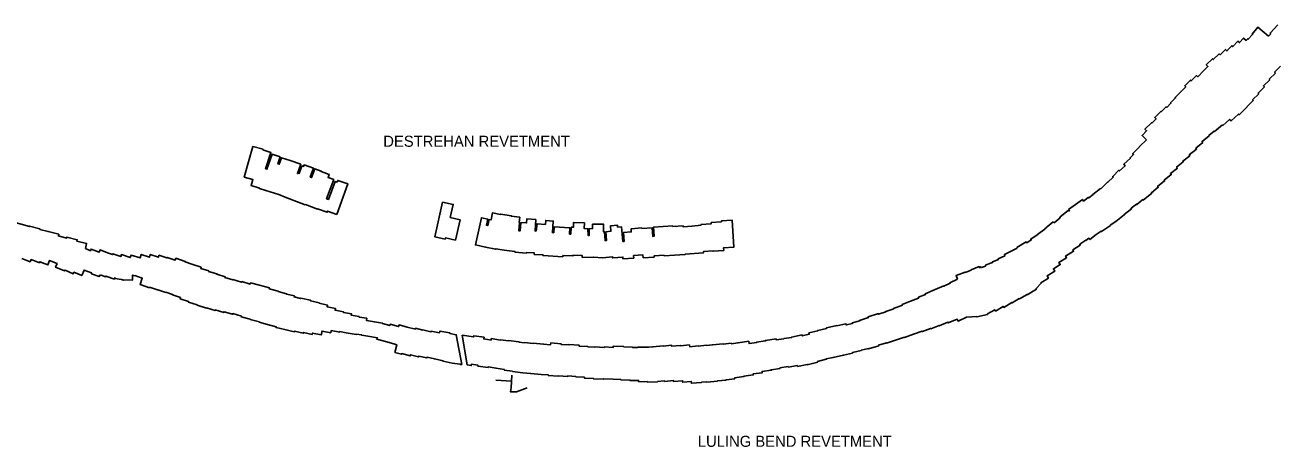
# Model space of a CAD drawing. Extents: x 2650582 to 3923188, y 277893 to 989177.
# Drawn here: x 3587538 to 3605630, y 520725 to 526834 of the extents above; entities that cross this region are included whole.
import ezdxf

# ---------------------------------------------------------------- set-up
doc = ezdxf.new("R2010")
doc.units = 0
doc.layers.add('Level 3', color=7, linetype='Continuous')

msp = doc.modelspace()

# ---------------------------------------------------------------- linework, layer by layer
at = {"layer": 'Level 3'}
for p, q in [((3597395, 522195), (3597395, 522195)), ((3594345, 521695), (3594574, 521678))]:
    msp.add_line(p, q, dxfattribs=at)
for points in [[(3605524, 526674), (3605370, 526803), (3605285, 526702), (3605293, 526694), (3605230, 526627), (3605223, 526634), (3605201, 526611), (3605163, 526645), (3605103, 526578), (3605081, 526599), (3605005, 526520), (3604991, 526534), (3604920, 526459), (3604898, 526481), (3604821, 526403), (3604808, 526416), (3604724, 526332), (3604711, 526346), (3604623, 526258), (3604647, 526234), (3604580, 526168), (3604580, 526168), (3604498, 526085), (3604480, 526102), (3604403, 526025), (3604392, 526036), (3604310, 525954), (3604326, 525938), (3604260, 525872), (3604258, 525873), (3604171, 525785), (3604178, 525777), (3604107, 525706), (3604112, 525701), (3604051, 525640), (3604042, 525650), (3603970, 525578), (3603966, 525582), (3603878, 525495), (3603897, 525476), (3603835, 525414), (3603830, 525419), (3603736, 525326), (3603760, 525302), (3603694, 525236), (3603757, 525173)], [(3605656, 526834), (3605545, 526717), (3605555, 526707), (3605524, 526674)], [(3604858, 525387), (3604864, 525380), (3604960, 525468), (3604982, 525445), (3605089, 525543), (3605098, 525534), (3605213, 525647), (3605209, 525651), (3605301, 525742), (3605293, 525751), (3605382, 525839), (3605372, 525849), (3605462, 525938), (3605448, 525952), (3605540, 526042), (3605532, 526049), (3605623, 526138), (3605609, 526152), (3605697, 526238)], [(3604574, 525131), (3604561, 525148), (3604663, 525229), (3604659, 525234), (3604736, 525296), (3604740, 525291), (3604858, 525387)], [(3590831, 525075), (3590709, 524630), (3590834, 524596), (3590807, 524512), (3590929, 524470), (3590928, 524466), (3591019, 524436), (3591207, 524378), (3591300, 524343), (3591299, 524340), (3591591, 524231), (3591593, 524234), (3591766, 524169), (3591769, 524174), (3591907, 524123), (3591913, 524139), (3592049, 524092)], [(3592049, 524092), (3592206, 524536), (3592060, 524585), (3592050, 524559), (3592021, 524568), (3591925, 524310), (3591900, 524319), (3592002, 524596), (3591922, 524625), (3591938, 524669), (3591820, 524713), (3591821, 524719), (3591730, 524752), (3591682, 524625), (3591664, 524631), (3591710, 524760), (3591574, 524808), (3591566, 524786), (3591542, 524794), (3591501, 524682), (3591486, 524687), (3591483, 524682), (3591478, 524684), (3591526, 524817), (3591373, 524873), (3591371, 524870), (3591247, 524912), (3591215, 524817), (3591196, 524823), (3591227, 524923), (3591110, 524962), (3591037, 524745), (3591016, 524752), (3591094, 524989), (3590979, 525027), (3590981, 525035), (3590831, 525075)], [(3601460, 522642), (3601458, 522651), (3601564, 522711), (3601576, 522692), (3601687, 522760), (3601695, 522747), (3601809, 522817), (3601813, 522810), (3601918, 522874), (3601922, 522868), (3602030, 522934), (3602033, 522930), (3602166, 523012), (3602161, 523020), (3602236, 523098), (3602230, 523104), (3602338, 523170), (3602319, 523201), (3602434, 523271), (3602412, 523305), (3602511, 523366), (3602492, 523397), (3602603, 523465), (3602588, 523489), (3602702, 523559), (3602690, 523579), (3602800, 523647), (3602792, 523660), (3602879, 523720), (3602882, 523716), (3602925, 523746), (3602940, 523728), (3603030, 523801), (3603102, 523850), (3603106, 523844), (3603235, 523932), (3603233, 523934), (3603313, 523989), (3603315, 523987), (3603437, 524084), (3603433, 524089), (3603540, 524174), (3603534, 524181), (3603611, 524242), (3603617, 524235), (3603705, 524306), (3603710, 524300), (3603834, 524399), (3603830, 524405), (3603928, 524484), (3603919, 524496), (3604020, 524576), (3604013, 524586), (3604115, 524668), (3604104, 524682), (3604205, 524763), (3604194, 524778), (3604290, 524855), (3604284, 524863), (3604383, 524942), (3604375, 524952), (3604483, 525037), (3604472, 525050), (3604574, 525131)], [(3603757, 525173), (3603655, 525073), (3603657, 525071), (3603556, 524971), (3603570, 524957), (3603520, 524911), (3603525, 524906), (3603429, 524817), (3603448, 524796), (3603367, 524721), (3603358, 524730), (3603269, 524642), (3603278, 524633), (3603199, 524557), (3603196, 524560), (3603096, 524464), (3603094, 524466), (3602982, 524382), (3602985, 524378), (3602922, 524331), (3602916, 524339), (3602847, 524286), (3602831, 524308), (3602730, 524237), (3602731, 524236), (3602628, 524164)], [(3593578, 524270), (3593463, 523768), (3593615, 523734), (3593619, 523752), (3593762, 523720)], [(3593762, 523720), (3593830, 524015), (3593688, 524048), (3593732, 524236), (3593578, 524270)], [(3602628, 524164), (3602644, 524142), (3602640, 524140), (3602630, 524153), (3602504, 524050), (3602510, 524043), (3602421, 523971), (3602410, 523984), (3602322, 523911), (3602307, 523902), (3602308, 523900), (3602285, 523881), (3602286, 523880), (3602188, 523806), (3602190, 523805), (3602084, 523734), (3602092, 523722), (3602025, 523681), (3602017, 523694), (3601883, 523612), (3601888, 523605)], [(3588411, 523597), (3588427, 523673), (3588289, 523703), (3588294, 523725), (3588141, 523761), (3588138, 523750), (3588020, 523780), (3588026, 523806), (3587873, 523845), (3587872, 523843), (3587753, 523875), (3587754, 523881), (3587602, 523923), (3587601, 523917), (3587481, 523950), (3587481, 523951), (3587344, 523988), (3587345, 523992), (3587220, 524027), (3587223, 524036), (3587090, 524079)], [(3595318, 523498), (3595316, 523479), (3595031, 523496), (3595031, 523505), (3594902, 523514), (3594903, 523535), (3594791, 523542), (3594790, 523533), (3594622, 523546), (3594622, 523556), (3594470, 523573), (3594348, 523594), (3594346, 523588), (3594198, 523619), (3594198, 523616), (3594052, 523650), (3594138, 524043), (3594229, 524023), (3594212, 523934), (3594231, 523930), (3594250, 524019), (3594279, 524013), (3594301, 524115), (3594416, 524091), (3594417, 524097), (3594569, 524073), (3594569, 524065), (3594694, 524050), (3594686, 523976), (3594690, 523976), (3594681, 523854), (3594699, 523852), (3594709, 523973), (3594791, 523968), (3594795, 524027), (3594925, 524018), (3594914, 523852), (3594932, 523850), (3594943, 523958), (3595064, 523948), (3595069, 524004), (3595177, 523996), (3595165, 523828), (3595185, 523827), (3595192, 523913), (3595415, 523900), (3595413, 523808), (3595432, 523807)], [(3595432, 523807), (3595437, 523905), (3595468, 523905), (3595471, 523975), (3595628, 523968), (3595625, 523886), (3595679, 523885), (3595681, 523787), (3595699, 523788), (3595699, 523884), (3595746, 523886), (3595747, 523949), (3595902, 523952), (3595903, 523840), (3595917, 523841), (3595926, 523712), (3595946, 523713), (3595939, 523842), (3596011, 523848), (3596007, 523928), (3596107, 523936), (3596109, 523909), (3596164, 523913), (3596182, 523700), (3596201, 523701), (3596192, 523829), (3596306, 523839), (3596305, 523884), (3596458, 523897), (3596460, 523889), (3596607, 523898), (3596617, 523774), (3596635, 523775), (3596626, 523906), (3596906, 523925), (3596907, 523918), (3597056, 523928), (3597058, 523912), (3597184, 523921), (3597183, 523924), (3597315, 523935), (3597314, 523947), (3597462, 523958), (3597462, 523974), (3597610, 523986), (3597609, 523999), (3597765, 524010), (3597790, 523619), (3597642, 523610), (3597644, 523570), (3597488, 523558), (3597488, 523564), (3597350, 523553), (3597351, 523536), (3597084, 523515), (3597084, 523510), (3596930, 523500), (3596929, 523504), (3596780, 523494), (3596780, 523502), (3596635, 523492), (3596636, 523475), (3596479, 523464), (3596474, 523506), (3596340, 523496), (3596341, 523461), (3596186, 523451), (3596184, 523474), (3596038, 523462), (3596036, 523477), (3595891, 523465), (3595759, 523474), (3595758, 523471), (3595598, 523470), (3595597, 523497), (3595462, 523502), (3595462, 523492), (3595318, 523498)], [(3601888, 523605), (3601801, 523559), (3601801, 523558), (3601703, 523511), (3601711, 523493), (3601612, 523449), (3601617, 523438), (3601529, 523404), (3601531, 523397), (3601489, 523381), (3601488, 523383), (3601477, 523376), (3601430, 523358), (3601433, 523349), (3601416, 523339), (3601373, 523323), (3601366, 523333), (3601344, 523319), (3601338, 523336), (3601222, 523291), (3601224, 523286), (3601136, 523252), (3601134, 523257), (3601004, 523206), (3601023, 523156)], [(3587492, 523454), (3587612, 523406), (3587625, 523439), (3587745, 523392), (3587751, 523408), (3587870, 523361), (3587894, 523425), (3588002, 523380), (3587980, 523327), (3588111, 523273), (3588116, 523285), (3588235, 523234), (3588244, 523254), (3588357, 523206), (3588392, 523287), (3588501, 523245), (3588497, 523234), (3588610, 523192), (3588618, 523215), (3588635, 523208)], [(3588731, 523536), (3588623, 523578), (3588610, 523544), (3588492, 523590), (3588483, 523567), (3588411, 523597)], [(3593857, 521918), (3593775, 522350), (3593682, 522368), (3593683, 522376), (3593538, 522404), (3593533, 522378), (3593410, 522402), (3593408, 522392), (3593290, 522419), (3593290, 522417), (3593186, 522444), (3593183, 522432), (3593067, 522462), (3593066, 522461), (3592947, 522493), (3592941, 522469), (3592818, 522503), (3592813, 522482), (3592708, 522511), (3592709, 522516), (3592590, 522535), (3592591, 522538), (3592475, 522557), (3592480, 522588), (3592369, 522606), (3592370, 522614), (3592257, 522632), (3592261, 522652), (3592143, 522674), (3592144, 522681), (3592021, 522705), (3592027, 522732), (3591906, 522755), (3591911, 522780), (3591793, 522805), (3591794, 522812), (3591667, 522841), (3591669, 522849), (3591525, 522882), (3591523, 522874), (3591429, 522897), (3591433, 522913), (3591320, 522940), (3591321, 522944), (3591200, 522977), (3591200, 522979), (3591069, 523015), (3591073, 523029), (3590929, 523068), (3590929, 523066), (3590800, 523101), (3590795, 523083), (3590674, 523120), (3590671, 523110), (3590542, 523148), (3590541, 523143), (3590430, 523177), (3590434, 523190), (3590311, 523227), (3590312, 523232), (3590192, 523268), (3590194, 523273), (3590079, 523310), (3590085, 523328), (3589951, 523374), (3589950, 523372), (3589852, 523405), (3589854, 523411), (3589719, 523457), (3589711, 523431), (3589594, 523470), (3589591, 523462), (3589475, 523501), (3589466, 523473), (3589350, 523512), (3589336, 523472), (3589219, 523514), (3589201, 523462), (3589072, 523504), (3589060, 523467), (3588931, 523510), (3588922, 523482), (3588810, 523522), (3588805, 523510), (3588731, 523536)], [(3588635, 523208), (3588637, 523213), (3588704, 523189), (3588708, 523200), (3588830, 523157), (3588837, 523178), (3588835, 523165), (3588932, 523149), (3588960, 523140), (3588961, 523143), (3589092, 523140), (3589094, 523214), (3589124, 523204), (3589125, 523206), (3589233, 523167), (3589203, 523077), (3589338, 523031), (3589340, 523037), (3589456, 522998), (3589457, 523001), (3589572, 522962), (3589573, 522966), (3589672, 522933), (3589670, 522927), (3589786, 522887), (3589781, 522871), (3589904, 522830), (3589901, 522822), (3590029, 522782), (3590028, 522776), (3590163, 522735), (3590164, 522738), (3590287, 522701), (3590289, 522709), (3590413, 522672), (3590416, 522683), (3590540, 522646), (3590543, 522656), (3590668, 522618), (3590666, 522609), (3590795, 522574), (3590794, 522573), (3590927, 522537), (3590926, 522533), (3591047, 522500), (3591046, 522497), (3591171, 522464), (3591169, 522455), (3591313, 522420), (3591313, 522422), (3591431, 522393), (3591433, 522401), (3591561, 522372), (3591564, 522384), (3591691, 522355), (3591696, 522375), (3591822, 522349), (3591833, 522403), (3591960, 522379), (3591966, 522411), (3592089, 522388), (3592090, 522396), (3592182, 522378), (3592182, 522378), (3592328, 522354), (3592329, 522361), (3592409, 522348), (3592408, 522342), (3592555, 522318), (3592555, 522320), (3592633, 522307), (3592627, 522286), (3592750, 522252), (3592750, 522251), (3592873, 522218), (3592872, 522218), (3592917, 522206), (3592887, 522095), (3592984, 522068), (3592986, 522077), (3593109, 522045), (3593113, 522060), (3593229, 522029), (3593232, 522040), (3593349, 522014), (3593352, 522024), (3593459, 522003), (3593458, 522000), (3593585, 521975), (3593583, 521967), (3593715, 521941), (3593715, 521940), (3593830, 521924), (3593830, 521921), (3593857, 521918)], [(3601023, 523156), (3600915, 523104), (3600920, 523095), (3600828, 523051), (3600825, 523058), (3600699, 523003), (3600699, 523005), (3600558, 522944), (3600563, 522933), (3600458, 522892), (3600462, 522882), (3600343, 522835), (3600343, 522835), (3600224, 522790), (3600228, 522780), (3600100, 522732), (3600103, 522726), (3599987, 522689), (3599989, 522682), (3599883, 522648), (3599880, 522657), (3599732, 522610), (3599736, 522599), (3599607, 522558), (3599609, 522551), (3599504, 522524), (3599506, 522515), (3599414, 522492), (3599410, 522509), (3599280, 522480), (3599280, 522483), (3599129, 522449), (3599131, 522442), (3599003, 522414), (3599005, 522408), (3598875, 522376), (3598879, 522358), (3598779, 522333), (3598777, 522347), (3598625, 522316), (3598626, 522311), (3598513, 522294), (3598514, 522292), (3598402, 522275), (3598400, 522289), (3598247, 522269), (3598248, 522262), (3598119, 522245), (3598120, 522236), (3598009, 522222), (3598004, 522256), (3597850, 522235), (3597851, 522232), (3597753, 522219), (3597752, 522228), (3597634, 522216), (3597634, 522219), (3597480, 522206), (3597480, 522202), (3597395, 522195)], [(3597396, 521670), (3597397, 521666), (3597551, 521679), (3597551, 521683), (3597676, 521693), (3597676, 521700), (3597802, 521713), (3597801, 521726), (3597936, 521745), (3597936, 521752), (3598069, 521769), (3598067, 521783), (3598201, 521801), (3598199, 521819), (3598330, 521837), (3598329, 521843), (3598458, 521861), (3598456, 521872), (3598575, 521890), (3598576, 521883), (3598710, 521904), (3598712, 521891), (3598850, 521920), (3598851, 521915), (3599002, 521951), (3598999, 521964), (3599126, 521995), (3599124, 522000), (3599225, 522023), (3599225, 522020), (3599376, 522053), (3599375, 522057), (3599505, 522086), (3599504, 522091), (3599632, 522124), (3599632, 522125), (3599735, 522151), (3599737, 522145), (3599885, 522192), (3599883, 522200), (3599995, 522235), (3599996, 522230), (3600144, 522277), (3600144, 522278), (3600257, 522314), (3600259, 522309), (3600386, 522357), (3600386, 522357), (3600513, 522404), (3600517, 522395), (3600636, 522441), (3600638, 522437), (3600758, 522484), (3600760, 522479), (3600886, 522534), (3600891, 522522), (3601018, 522578), (3601032, 522548), (3601153, 522605), (3601154, 522604), (3601160, 522607), (3601303, 522616), (3601305, 522609), (3601460, 522642)], [(3597395, 522195), (3597394, 522198), (3597273, 522186), (3597273, 522188), (3597151, 522177), (3597148, 522203), (3597020, 522191), (3597020, 522195), (3596890, 522183), (3596888, 522198), (3596766, 522186), (3596766, 522189), (3596617, 522177), (3596618, 522174), (3596553, 522172), (3596553, 522172), (3596403, 522170), (3596403, 522166), (3596326, 522164), (3596326, 522170), (3596196, 522176), (3596196, 522180), (3596046, 522187), (3596046, 522168), (3595914, 522174), (3595914, 522167), (3595780, 522174), (3595780, 522172), (3595676, 522177), (3595676, 522181), (3595552, 522187), (3595553, 522199), (3595403, 522211), (3595403, 522202), (3595291, 522210), (3595292, 522220), (3595142, 522232), (3595140, 522206), (3595037, 522214), (3595037, 522216), (3594887, 522228), (3594887, 522224), (3594762, 522236), (3594761, 522233), (3594680, 522245), (3594680, 522248), (3594531, 522269), (3594530, 522261), (3594415, 522279), (3594414, 522273), (3594281, 522294), (3594278, 522274), (3594172, 522291), (3594176, 522313), (3594029, 522336), (3594026, 522319), (3593858, 522345)], [(3593858, 522345), (3593932, 521915), (3593992, 521905), (3593995, 521923), (3594088, 521908), (3594087, 521897), (3594235, 521874), (3594237, 521886), (3594350, 521868), (3594349, 521865), (3594471, 521845), (3594470, 521839), (3594587, 521822), (3594587, 521819), (3594736, 521798), (3594737, 521801), (3594853, 521789), (3594853, 521787), (3595003, 521775), (3595003, 521777), (3595106, 521769), (3595105, 521762), (3595255, 521751), (3595255, 521755), (3595387, 521744), (3595388, 521754), (3595506, 521744), (3595505, 521740), (3595629, 521735), (3595629, 521724), (3595759, 521718), (3595759, 521713), (3595909, 521706), (3595909, 521713), (3596043, 521707), (3596043, 521708), (3596154, 521703), (3596154, 521700), (3596289, 521693), (3596289, 521687), (3596411, 521690), (3596412, 521671), (3596536, 521673), (3596536, 521664), (3596686, 521671), (3596686, 521673), (3596787, 521682), (3596788, 521675), (3596918, 521687), (3596919, 521672), (3597048, 521684), (3597051, 521662), (3597173, 521674), (3597175, 521647), (3597323, 521661), (3597323, 521663), (3597396, 521670)], [(3594578, 521763), (3594570, 521583), (3594560, 521523), (3594645, 521522), (3594798, 521580)]]:
    msp.add_lwpolyline(points, dxfattribs=at)

# ---------------------------------------------------------------- texts
for s, p in [('DESTREHAN REVETMENT', (3592719, 525071)), ('LULING BEND REVETMENT', (3597268, 520728))]:
    msp.add_text(s, height=160, dxfattribs=at).set_placement(p)

doc.saveas('drawing.dxf')
